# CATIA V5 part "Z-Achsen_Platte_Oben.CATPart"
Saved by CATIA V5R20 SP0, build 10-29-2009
Part number: Z-Achsen_Platte_Oben
Bounding box of the stored display mesh (mm): x -71.941 to 5.941, y -70 to 70, z 0 to 20
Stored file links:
  C:\Users\Andi\Desktop\Offene Projekte\Plasmacutter\Z-Achse\Z-Achsen_Platte_Oben.CATPart
  C:\Program Files\Dassault Systemes\B20\win_b64\reffiles\standard\MetricThickPitch.txt
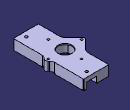
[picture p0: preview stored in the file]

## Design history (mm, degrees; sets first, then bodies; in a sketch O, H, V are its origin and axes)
Body1 (main body)
  Sketch1 on xy-plane, origin (0, 0, 0), H (1, 0, 0), V (0, 1, 0)
    point P1 (0, 70)
    line L1 (0, 70) -> (-50, 70)
    line L2 (-50, 70) -> (-50, 28.1543)
    line L3 (-50, -70) -> (0, -70)
    line L4 (0, -70) -> (0, -12.1543)
    circle A1 centre (-33, 0) radius 14
    point P5 (-33, 0)
    circle A2 centre (-16, 60) radius 2.65
    point P6 (-16, 60)
    circle A3 centre (-16, -60) radius 2.65
    line L5 (-70.4767, 3.5355) -> (-52.9289, 21.0833)
    point P8 (-74.0122, 0)
    line L6 (2.9289, 5.0833) -> (4.4767, 3.5355)
    line L7 (4.4767, -3.5355) -> (2.9289, -5.0833)
    line L8 (-52.9289, -21.0833) -> (-70.4767, -3.5355)
    point P9 (8.0122, 0)
    line L9 (0, 12.1543) -> (0, 70)
    line L10 (-50, -28.1543) -> (-50, -70)
    arc A4 centre (-60, 28.1543) radius 10 from (-50, 28.1543) to (-52.9289, 21.0833) cw
    arc A5 centre (-60, -28.1543) radius 10 from (-50, -28.1543) to (-52.9289, -21.0833) ccw
    arc A6 centre (10, -12.1543) radius 10 from (0, -12.1543) to (2.9289, -5.0833) cw
    arc A7 centre (10, 12.1543) radius 10 from (0, 12.1543) to (2.9289, 5.0833) ccw
    arc A8 centre (0.9411, 0) radius 5 from (4.4767, -3.5355) to (4.4767, 3.5355) ccw
    arc A9 centre (-66.9411, 0) radius 5 from (-70.4767, 3.5355) to (-70.4767, -3.5355) ccw
    distance L2 L4 = 50
    distance L3 L1 = 140
    radius A1 = 14
    distance P6 L4 = 16
    distance P5 L4 = 33
    distance P6 L1 = 10
    radius A2 = 2.65
    distance L7 L5 = 58
    radius A4 = 10
    radius A5 = 10 {= Sketch1.radius(A4)}
    radius A6 = 10 {= Sketch1.radius(A4)}
    radius A7 = 10 {= Sketch1.radius(A4)}
    radius A8 = 5
    radius A9 = 5 {= Sketch1.radius(A8)}
    coincidence: P1 V, P5 H, P8 H, P9 H, L4 L9, L2 L10, L7 P9, L6 P9, L5 P8, L8 P8
    horizontal: L1 H, L3 H
    vertical: L2 V, L4 V, L9 V, L10 V
    symmetry: L1 L3 H, A3 A2 H, L6 L7 H
    parallelism: L8 L6
    perpendicularity: L5 L6
    equidistance: L6 L8 P5
    tangency: A4 L2, A4 L5, A5 L10, A5 L8, A6 L4, A6 L7, A7 L9, A7 L6, A8 L7, A8 L6, A9 L5, A9 L8
  Pad1: profile Sketch1, direction (0, 0, 1), length 20
  Fillet1: radius 1, on edge [face of Pad1 from Sketch1.L2 | face of Pad1 from Sketch1.L1]; edge [face of Pad1 from Sketch1.L4 | face of Pad1 from Sketch1.L3]; edge [face of Pad1 from Sketch1.L1 | face of Pad1 from Sketch1.L9]; edge [face of Pad1 from Sketch1.L3 | face of Pad1 from Sketch1.L10]
  Sketch2 on end face of Pad1, origin (0, 0, 20), H (1, 0, 0), V (0, 1, 0)
    construction line L1 (-66.333, 0) -> (-33, 33.333)
    point P1 (-66.333, 0)
    construction line L2 (-33, 33.333) -> (0.333, 0)
    construction line L3 (0.333, 0) -> (-33, -33.333)
    construction line L4 (-33, -33.333) -> (-66.333, 0)
    point P3 (0.333, 0)
    reference projected point E1 (-33, 0) from axis of face of Pad1 from Sketch1.A1
    distance L2 L4 = 47.14
    coincidence: P1 H, P3 H
    parallelism: L1 L3
    perpendicularity: L1 L2
    symmetry: L3 L2 H
    equidistance: L2 L4 E1
  Sketch3 on end face of Pad1, origin (2.2962, -0.4505, 20), H (1, 0, 0), V (0, 1, 0)
    point P1 (-68.6292, 0.4505)
    reference projected point E1 (-68.6292, 0.4505) from Sketch2.P1
    coincidence: P1 E1
  Hole1: placed by Sketch3, at (-66.333, 0, 20) direction (0, 0, -1), diameter 4.134, through (limit type 6), threaded "M5", thread diameter 5, thread depth 20, pitch 0.8
  UserPattern1: of Hole1, copies 4, at the points of Sketch2
  Sketch4 on start face of Pad1, origin (-54.5758, -4.8678, 0), H (1, 0, 0), V (0, -1, 0)
    point P1 (21.5758, -4.8678)
    reference projected point E1 (21.5758, -4.8678) from axis of face of Pad1 from Sketch1.A1
    coincidence: P1 E1
  Hole2: placed by Sketch4, at (-33, 0, 0) direction (0, 0, 1), diameter 32, depth 17.7
  Sketch5 on start face of Pad1, origin (0, 0, 0), H (1, 0, 0), V (0, -1, 0)
    line L1 (-70.4767, 3.5355) -> (-36.5355, 37.4767)
    point P1 (-74.0122, 0)
    line L2 (-29.4645, 37.4767) -> (4.4767, 3.5355)
    line L3 (4.4767, -3.5355) -> (-29.4645, -37.4767)
    line L4 (-36.5355, -37.4767) -> (-70.4767, -3.5355)
    point P2 (8.0122, 0)
    reference projected point E1 (-33, 0) from axis of face of Hole2
    reference intersected line E2 (-70.4767, 3.5355) -> (-52.9289, 21.0833) from face of Pad1 from Sketch1.L8
    arc A1 centre (-66.9411, 0) radius 5 from (-70.4767, 3.5355) to (-70.4767, -3.5355) ccw
    arc A2 centre (-33, 33.9411) radius 5 from (-36.5355, 37.4767) to (-29.4645, 37.4767) cw
    arc A3 centre (0.9411, 0) radius 5 from (4.4767, 3.5355) to (4.4767, -3.5355) cw
    arc A4 centre (-33, -33.9411) radius 5 from (-29.4645, -37.4767) to (-36.5355, -37.4767) cw
    radius A1 = 5
    radius A2 = 5 {= Sketch5.radius(A1)}
    radius A3 = 5 {= Sketch5.radius(A1)}
    radius A4 = 5 {= Sketch5.radius(A1)}
    coincidence: P1 H, P2 H, L1 E2, L1 P1, L4 P1, L2 P2, L3 P2
    parallelism: L4 L2, L1 L3
    perpendicularity: L1 L2
    symmetry: L2 L3 H
    equidistance: L2 L4 E1
    tangency: A1 L1, A1 L4, A2 L1, A2 L2, A3 L2, A3 L3, A4 L3, A4 L4
  Pocket1: profile Sketch5, direction (0, 0, 1), length 2
  Fillet2: radius 2, on edge [face of Pocket1 from Sketch5.L4 | face of Pad1 from Sketch1.A4]; edge [face of Pad1 from Sketch1.A5 | face of Pocket1 from Sketch5.L1]; edge [face of Pocket1 from Sketch5.L2 | face of Pad1 from Sketch1.A6]; edge [face of Pad1 from Sketch1.A7 | face of Pocket1 from Sketch5.L3]
  Sketch6 on start face of Pad1, origin (0, 0, 0), H (1, 0, 0), V (0, -1, 0)
    line L1 (-26.25, 70) -> (-5.75, 70)
    line L2 (-5.75, 70) -> (-5.75, 52.5)
    line L3 (-8.75, 49.5) -> (-23.25, 49.5)
    line L4 (-26.25, 52.5) -> (-26.25, 70)
    reference projected point E1 (-16, 60) from axis of face of Pad1 from Sketch1.A3
    reference intersected line E2 (-50, 70) -> (0, 70) from face of Pad1 from Sketch1.L3
    arc A1 centre (-23.25, 52.5) radius 3 from (-23.25, 49.5) to (-26.25, 52.5) cw
    arc A2 centre (-8.75, 52.5) radius 3 from (-5.75, 52.5) to (-8.75, 49.5) cw
    distance L3 L1 = 20.5
    distance L4 L2 = 20.5 {= Sketch6.distance(L3 L1)}
    radius A1 = 3
    radius A2 = 3 {= Sketch6.radius(A1)}
    horizontal: L1 H, L3 H
    vertical: L2 V, L4 V
    equidistance: L4 L2 E1
    coincidence: E2 L1
    tangency: A1 L3, A1 L4, A2 L2, A2 L3
  Pocket2: profile Sketch6, direction (0, 0, 1), length 12
  Sketch7 on start face of Pad1, origin (0, 0, 0), H (1, 0, 0), V (0, -1, 0)
    line L1 (-50, 63.5) -> (-46, 63.5)
    line L2 (-46, 56.5) -> (-50, 56.5)
    line L3 (-50, 56.5) -> (-50, 63.5)
    arc A1 centre (-46, 60) radius 3.5 from (-46, 56.5) to (-46, 63.5) ccw
    point P5 (-46, 60)
    reference intersected line E1 (-50, 28.1543) -> (-50, 70) from face of Pad1 from Sketch1.L10
    reference intersected line E2 through (0, 0) direction (1, 0) from zx-plane
    radius A1 = 3.5
    distance L3 P5 = 4
    distance P5 E2 = 60
    horizontal: L1 H, L2 H
    vertical: L3 V
    tangency: A1 L2, A1 L1
    coincidence: E1 L3
  Pocket3: profile Sketch7, direction (0, 0, 1), length 6
  Mirror1: of Pocket2, Pocket3, about zx-plane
